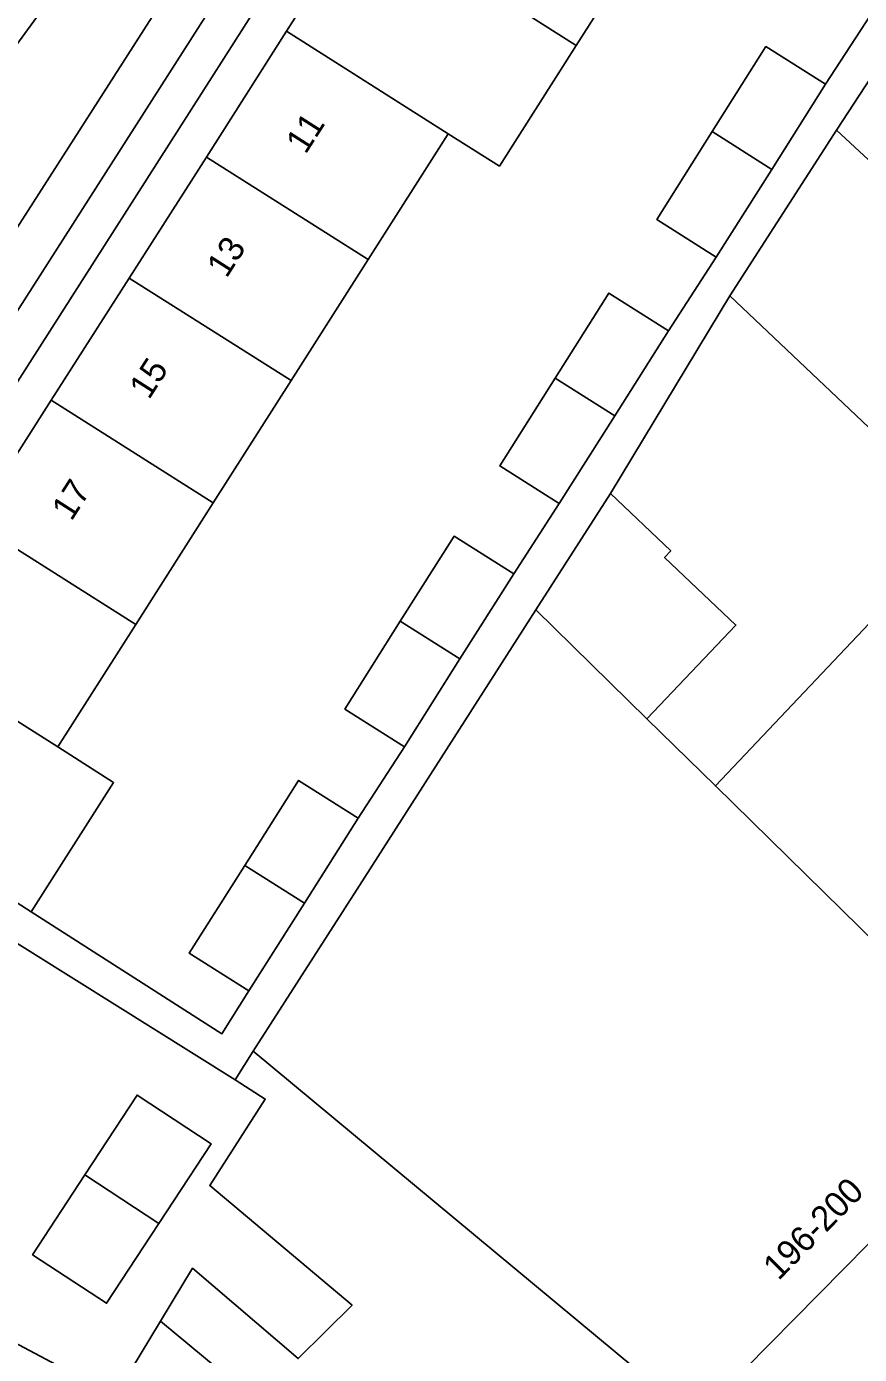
# Model space of a CAD drawing. Extents: x 160102 to 160934, y 382045 to 382923.
# Drawn here: x 160431 to 160464.1, y 382187.9 to 382240.6 of the extents above; entities that cross this region are included whole.
import ezdxf

# ---------------------------------------------------------------- set-up
doc = ezdxf.new("R2010")
doc.units = 0
for name, color, linetype in [('IMGEO_Erf', 7, 'Continuous'), ('IMGEO_Pand', 7, 'Continuous'), ('IMGEO_Pand_nummerreeks', 7, 'Continuous'), ('IMGEO_Parkeervlak_open', 7, 'Continuous'), ('IMGEO_Rijbaan_lokaal_open', 7, 'Continuous'), ('IMGEO_Voetpad_open', 7, 'Continuous')]:
    doc.layers.add(name, color=color, linetype=linetype)

msp = doc.modelspace()

# ---------------------------------------------------------------- linework, layer by layer
at = {"layer": 'IMGEO_Erf'}
for points in [[(160438.148, 382235.408), (160441.334, 382240.397), (160444.39, 382245.181), (160447.468, 382250), (160447.522, 382250.085), (160450.518, 382254.775), (160453.656, 382259.688), (160456.593, 382264.286), (160456.504, 382264.389), (160456.68, 382264.653), (160455.515, 382265.414), (160445.664, 382250), (160421.255, 382211.804), (160422.477, 382211.023), (160422.651, 382211.303), (160425.806, 382216.085), (160428.908, 382220.942), (160431.99, 382225.767), (160435.083, 382230.609)], [(160477.82, 382247.311), (160474.909, 382250), (160473.904, 382250.928), (160470.048, 382247.005), (160463.167, 382236.476), (160466.789, 382233.109), (160466.884, 382233.21), (160472.534, 382239.178), (160472.665, 382239.316), (160471.471, 382240.412), (160474.396, 382243.668)], [(160458.937, 382229.907), (160454.187, 382222.06), (160456.588, 382219.786), (160456.34, 382219.524), (160459.171, 382216.842), (160455.642, 382213.116), (160458.356, 382210.456), (160466.338, 382218.884), (160467.958, 382217.35), (160474.878, 382210.798), (160478.508, 382207.36), (160479.982, 382208.986), (160479.765, 382209.193), (160479.979, 382209.419), (160476.349, 382212.857), (160469.685, 382219.171), (160469.961, 382219.462)], [(160433.323, 382195.027), (160435.399, 382198.192), (160438.339, 382196.264), (160436.263, 382193.099), (160434.186, 382189.932), (160431.246, 382191.86)]]:
    msp.add_lwpolyline(points, close=True, dxfattribs=at)
for points in [[(160455.806, 382244.499), (160452.833, 382239.836), (160449.78, 382235.048), (160447.755, 382236.331), (160444.574, 382231.34), (160441.512, 382226.538), (160438.425, 382221.693), (160435.347, 382216.865), (160432.249, 382212.005), (160434.463, 382210.592), (160431.19, 382205.463), (160438.764, 382200.629), (160439.837, 382202.324), (160437.47, 382203.822), (160439.673, 382207.304), (160441.808, 382210.678), (160444.176, 382209.18), (160446.013, 382212.012), (160443.646, 382213.51), (160445.849, 382216.993), (160447.984, 382220.366), (160450.352, 382218.868), (160452.162, 382221.659), (160449.795, 382223.157), (160451.998, 382226.64), (160454.133, 382230.013), (160456.501, 382228.515), (160458.394, 382231.438), (160456.027, 382232.936), (160458.23, 382236.419), (160460.365, 382239.792), (160462.733, 382238.294), (160464.513, 382241.037)], [(160435.138, 382187.258), (160436.329, 382189.226), (160437.598, 382191.324), (160441.794, 382187.739), (160443.937, 382189.855), (160438.281, 382194.603), (160440.486, 382198.033), (160439.287, 382198.801), (160428.096, 382205.789), (160426.258, 382202.279), (160427.973, 382201.381), (160426.404, 382198.652), (160424.932, 382196.091), (160423.326, 382196.932), (160421.55, 382193.541), (160421.394, 382193.622), (160421.287, 382193.417), (160421.223, 382193.294), (160422.612, 382192.566), (160433.243, 382186.941)]]:
    msp.add_lwpolyline(points, dxfattribs=at)
at = {"layer": 'IMGEO_Pand'}
for points in [[(160447.656, 382250), (160447.522, 382250.085), (160447.468, 382250), (160444.39, 382245.181), (160450.806, 382241.119), (160452.833, 382239.836), (160455.806, 382244.499), (160453.784, 382245.789), (160453.934, 382246.025)], [(160450.806, 382241.119), (160444.39, 382245.181), (160441.334, 382240.397), (160447.755, 382236.331), (160449.78, 382235.048), (160452.833, 382239.836)], [(160447.755, 382236.331), (160441.334, 382240.397), (160438.148, 382235.408), (160444.574, 382231.34)], [(160460.597, 382234.92), (160462.733, 382238.294), (160460.365, 382239.792), (160458.23, 382236.419)], [(160460.597, 382234.92), (160458.23, 382236.419), (160456.027, 382232.936), (160458.394, 382231.438)], [(160486.148, 382215.5), (160466.884, 382233.21), (160466.789, 382233.109), (160463.167, 382236.476), (160458.937, 382229.907), (160469.961, 382219.462), (160469.685, 382219.171), (160476.349, 382212.857), (160479.979, 382209.419), (160479.765, 382209.193), (160479.982, 382208.986), (160480.965, 382210.025), (160485.952, 382215.293)], [(160444.574, 382231.34), (160438.148, 382235.408), (160435.083, 382230.609), (160441.512, 382226.538)], [(160431.99, 382225.767), (160438.425, 382221.693), (160441.512, 382226.538), (160435.083, 382230.609)], [(160451.998, 382226.64), (160454.365, 382225.141), (160456.501, 382228.515), (160454.133, 382230.013)], [(160451.998, 382226.64), (160449.795, 382223.157), (160452.162, 382221.659), (160454.365, 382225.141)], [(160431.99, 382225.767), (160428.908, 382220.942), (160435.347, 382216.865), (160438.425, 382221.693)], [(160451.228, 382217.442), (160455.642, 382213.116), (160459.171, 382216.842), (160456.34, 382219.524), (160456.588, 382219.786), (160454.187, 382222.06)], [(160428.908, 382220.942), (160425.806, 382216.085), (160432.249, 382212.005), (160435.347, 382216.865)], [(160448.216, 382215.494), (160450.352, 382218.868), (160447.984, 382220.366), (160445.849, 382216.993)], [(160474.878, 382210.798), (160467.958, 382217.35), (160466.338, 382218.884), (160458.356, 382210.456), (160470.549, 382198.506), (160478.508, 382207.36)], [(160458.356, 382210.456), (160455.642, 382213.116), (160451.228, 382217.442), (160444.225, 382206.51), (160440.009, 382199.929), (160457.583, 382185.349), (160470.305, 382198.234), (160470.549, 382198.506)], [(160448.216, 382215.494), (160445.849, 382216.993), (160443.646, 382213.51), (160446.013, 382212.012)], [(160425.806, 382216.085), (160422.651, 382211.303), (160422.477, 382211.023), (160426.692, 382208.334), (160428.979, 382206.874), (160431.19, 382205.463), (160434.463, 382210.592), (160432.249, 382212.005)], [(160439.673, 382207.304), (160442.04, 382205.805), (160444.176, 382209.18), (160441.808, 382210.678)], [(160439.673, 382207.304), (160437.47, 382203.822), (160439.837, 382202.324), (160442.04, 382205.805)], [(160450.125, 382177.781), (160453.711, 382181.42), (160457.583, 382185.349), (160440.009, 382199.929), (160439.287, 382198.801), (160440.486, 382198.033), (160438.281, 382194.603), (160443.937, 382189.855), (160441.794, 382187.739), (160437.598, 382191.324), (160436.329, 382189.226)], [(160433.323, 382195.027), (160436.263, 382193.099), (160438.339, 382196.264), (160435.399, 382198.192)], [(160421.287, 382193.417), (160414.79, 382196.819), (160409.837, 382187.53), (160417.793, 382183.364), (160420.108, 382187.785), (160426.894, 382184.256), (160426.636, 382183.761), (160427.142, 382183.499), (160426.214, 382181.714), (160425.557, 382182.056), (160422.791, 382176.738), (160426.252, 382174.79), (160426.462, 382175.164), (160429.17, 382179.97), (160431.71, 382184.61), (160433.243, 382186.941), (160422.612, 382192.566), (160421.223, 382193.294)], [(160436.263, 382193.099), (160433.323, 382195.027), (160431.246, 382191.86), (160434.186, 382189.932)], [(160436.329, 382189.226), (160435.138, 382187.258), (160439.415, 382183.782), (160438.401, 382182.752), (160436.824, 382181.152), (160438.833, 382179.173), (160439.354, 382179.701), (160446.321, 382173.921), (160450.125, 382177.781)]]:
    msp.add_lwpolyline(points, close=True, dxfattribs=at)
at = {"layer": 'IMGEO_Parkeervlak_open'}
for points in [[(160447.572, 382259.078), (160446.36, 382257.139), (160441.774, 382250), (160441.342, 382249.327), (160430.325, 382232.106), (160428.504, 382228.728)], [(160429.164, 382228.86), (160430.014, 382228.317), (160443.874, 382250), (160447.575, 382255.79)]]:
    msp.add_lwpolyline(points, dxfattribs=at)
at = {"layer": 'IMGEO_Rijbaan_lokaal_open'}
msp.add_lwpolyline([(160435.617, 382246.74), (160430.195, 382239.286), (160428.862, 382237.478), (160420.631, 382224.771), (160420.174, 382223.892), (160417.42, 382218.914), (160412.676, 382210.188), (160410.459, 382205.975), (160410.382, 382205.828), (160408.529, 382202.431), (160405.31, 382196.514), (160408.318, 382194.865), (160411.454, 382200.674), (160417.329, 382211.549), (160417.989, 382212.757), (160418.097, 382212.953), (160419.921, 382215.791), (160428.504, 382228.728), (160430.325, 382232.106), (160441.342, 382249.327)], dxfattribs=at)
at = {"layer": 'IMGEO_Voetpad_open'}
for points in [[(160420.153, 382209.835), (160420.22, 382209.956), (160421.239, 382211.78), (160421.255, 382211.804), (160445.664, 382250), (160455.515, 382265.414), (160457.578, 382268.539), (160459.546, 382271.613), (160462.968, 382276.958), (160461.076, 382278.193), (160459.654, 382279.028)], [(160453.608, 382267.022), (160454.452, 382266.493), (160450.673, 382260.635), (160450.782, 382260.566), (160447.676, 382255.711), (160447.575, 382255.79), (160443.874, 382250), (160430.014, 382228.317), (160429.164, 382228.86)], [(160428.096, 382205.789), (160439.287, 382198.801), (160440.009, 382199.929), (160444.225, 382206.51), (160451.228, 382217.442), (160454.187, 382222.06), (160458.937, 382229.907), (160463.167, 382236.476), (160470.048, 382247.005)], [(160428.862, 382237.478), (160430.195, 382239.286), (160435.617, 382246.74), (160435.699, 382246.868)], [(160464.513, 382241.037), (160462.733, 382238.294), (160460.597, 382234.92), (160458.394, 382231.438), (160456.501, 382228.515), (160454.365, 382225.141), (160452.162, 382221.659), (160450.352, 382218.868), (160448.216, 382215.494), (160446.013, 382212.012), (160444.176, 382209.18), (160442.04, 382205.805), (160439.837, 382202.324), (160438.764, 382200.629), (160431.19, 382205.463), (160428.979, 382206.874)], [(160470.305, 382198.234), (160457.583, 382185.349), (160453.711, 382181.42), (160450.125, 382177.781), (160446.321, 382173.921), (160446.2, 382173.799), (160442.372, 382169.913), (160437.36, 382164.828), (160434.333, 382163.521)]]:
    msp.add_lwpolyline(points, dxfattribs=at)

# ---------------------------------------------------------------- texts
at = {"layer": 'IMGEO_Pand_nummerreeks'}
for s, rotation, p in [('11', 57.4327, (160442.089, 382235.485)), ('13', 57.4327, (160438.949, 382230.569)), ('15', 57.4327, (160435.87, 382225.749)), ('17', 57.4327, (160432.791, 382220.929)), ('196-200', 45.3668, (160460.866, 382190.809))]:
    msp.add_text(s, height=1, rotation=rotation, dxfattribs=at).set_placement(p)

doc.saveas('drawing.dxf')
